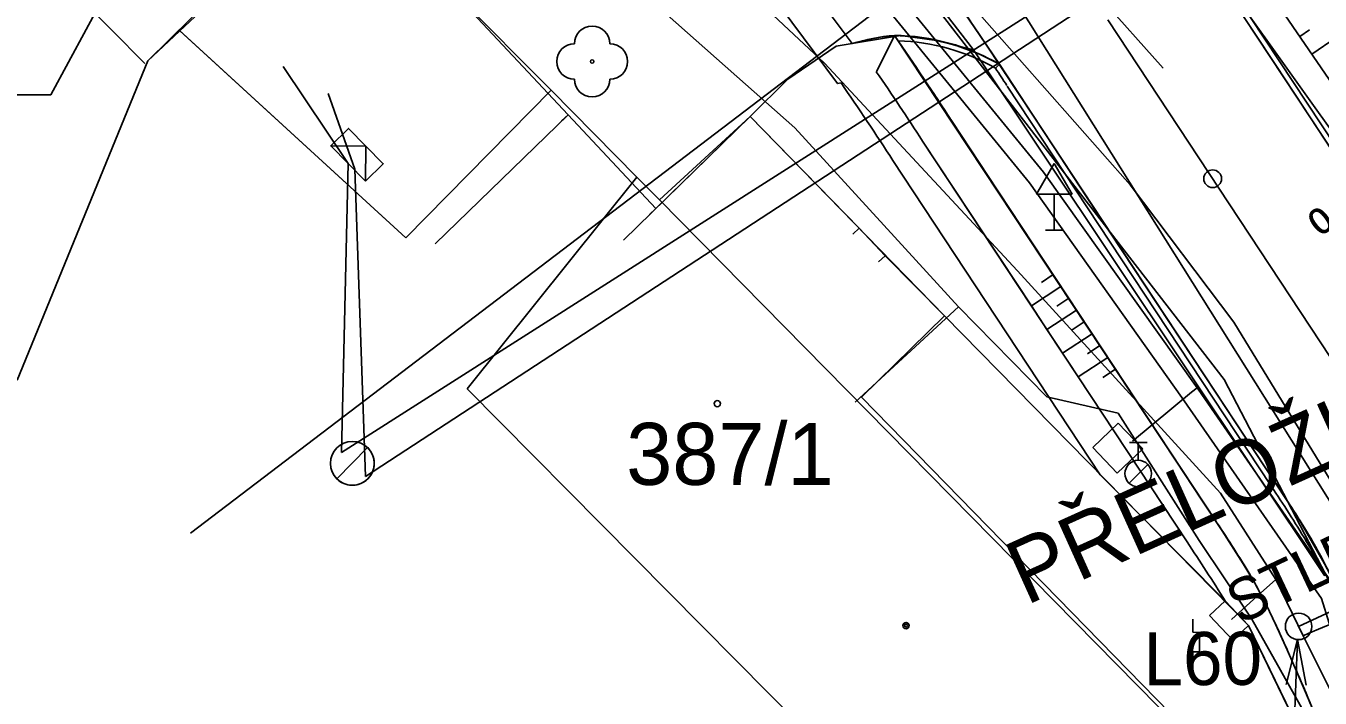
# Model space of a CAD drawing. Extents: x -643342 to -638635, y -1201752 to -1189948.
# Drawn here: x -639555.87 to -639519.33, y -1192610.36 to -1192591.39 of the extents above; entities that cross this region are included whole.
import ezdxf

# ---------------------------------------------------------------- set-up
doc = ezdxf.new("R2010")
doc.units = 0
for name, color, linetype in [('2', 7, 'Continuous'), ('42', 7, 'Continuous'), ('IS_EL_NN_NADZEMNÍ', 7, 'Continuous'), ('IS_EL_NN_PODZEMNÍ', 7, 'Continuous'), ('IS_PLYN_STL', 7, 'Continuous'), ('IS_TELEF_MISTNI_ZAMERENO', 7, 'Continuous'), ('IS_VODOVOD_PRIPOJKA DOMOVNÍ', 7, 'Continuous'), ('IS_VODOVOD_VAS', 7, 'Continuous'), ('IS_VODOVOD_ZRUSENY', 7, 'Continuous'), ('K-HRANICE_KN', 7, 'Continuous'), ('K-ČÍSLA_PARCEL', 7, 'Continuous'), ('N-CHODNIK', 7, 'Continuous'), ('N-HECTOMETRY', 7, 'Continuous'), ('N-KAN_DEST_TRASA-NÁVRH', 7, 'Continuous'), ('N-OBVOD STAVBY 06', 7, 'Continuous'), ('N-OSA', 7, 'Continuous'), ('N-SILNICE', 7, 'Continuous'), ('N-SJEZDY', 7, 'Continuous'), ('N-SO101_KLOPENI', 7, 'Continuous'), ('N-SRAFY_PLOCHY', 7, 'Continuous'), ('N-SVAHOVÁNÍ', 7, 'Continuous'), ('RWE_STL_RADY', 7, 'Continuous'), ('Vrstva 46', 7, 'Continuous'), ('Z-budovy', 7, 'Continuous'), ('Z-hrany_a_čáry', 7, 'Continuous'), ('Z-stromy', 7, 'Continuous'), ('Z-vchody_vjezdy', 7, 'Continuous'), ('Z-značky', 7, 'Continuous'), ('Z-šachty_poklopy', 7, 'Continuous')]:
    doc.layers.add(name, color=color, linetype=linetype)

# ---------------------------------------------------------------- blocks, each defined once
blk = doc.blocks.new('hecto2')
at = {"layer": 'N-HECTOMETRY'}
blk.add_circle((0, 0), 0.25, dxfattribs=at)

msp = doc.modelspace()

# ---------------------------------------------------------------- linework, layer by layer
at = {"layer": '2'}
msp.add_circle((-639519.932, -1192608.331), 0.375, dxfattribs=at)
at = {"layer": '42'}
for p, q in [((-639555.166, -1192593.331), (-639544.715, -1192573.992)), ((-639540.313, -1192573.957), (-639523.758, -1192592.58)), ((-639577.063, -1192593.331), (-639555.166, -1192593.331)), ((-639519.963, -1192608.704), (-639520.287, -1192609.969)), ((-639520.256, -1192616.346), (-639519.963, -1192608.704)), ((-639519.963, -1192608.704), (-639519.716, -1192609.987))]:
    msp.add_line(p, q, dxfattribs=at)
at = {"layer": 'IS_EL_NN_NADZEMNÍ'}
for p, q in [((-639520.2, -1192587.08), (-639546.28, -1192604.1)), ((-639521.55, -1192587.25), (-639546.96, -1192603.42)), ((-639546.96, -1192603.42), (-639546.77, -1192595.27)), ((-639546.28, -1192604.1), (-639546.58, -1192595.43))]:
    msp.add_line(p, q, dxfattribs=at)
for points in [[(-639546.279, -1192595.768), (-639546.271, -1192594.779), (-639547.26, -1192594.771)], [(-639547.09, -1192604.167), (-639546.224, -1192603.279)], [(-639546.224, -1192603.279), (-639547.09, -1192604.167)]]:
    msp.add_lwpolyline(points, dxfattribs=at)
msp.add_circle((-639546.65, -1192603.73), 0.62, dxfattribs=at)
for centre, radius, start, end in [((-639546.65, -1192603.73), 0.62, 224.818, 45.737), ((-639546.677, -1192603.71), 0.625, 42.6813, 43.6055)]:
    msp.add_arc(centre, radius, start, end, dxfattribs=at)
at = {"layer": 'IS_EL_NN_PODZEMNÍ'}
for p, q in [((-639546.77, -1192595.27), (-639548.6, -1192592.53)), ((-639546.58, -1192595.43), (-639547.33, -1192593.29))]:
    msp.add_line(p, q, dxfattribs=at)
msp.add_lwpolyline([(-639546.279, -1192595.768), (-639547.26, -1192594.771), (-639546.762, -1192594.279), (-639545.779, -1192595.277)], close=True, dxfattribs=at)
at = {"layer": 'IS_PLYN_STL'}
for points in [[(-639559.68, -1192568.38), (-639559.46, -1192568.55), (-639554.43, -1192572.9), (-639553.3, -1192573.86), (-639548.93, -1192577.94), (-639546.47, -1192580.23), (-639545.93, -1192580.74), (-639537.37, -1192588.65), (-639533.32, -1192592.44), (-639527.87, -1192598.3), (-639522.14, -1192604.57), (-639520.58, -1192607.01), (-639519.8, -1192608.6)], [(-639519.8, -1192608.6), (-639519.66, -1192608.53), (-639519.26, -1192608.36), (-639509.44, -1192604.37), (-639509.29, -1192604.31), (-639498.2, -1192598.48), (-639497.397, -1192598.104)], [(-639521.83, -1192608.14), (-639521.09, -1192607.47), (-639520.58, -1192607.01)], [(-639519.8, -1192608.6), (-639518.34, -1192611.53), (-639516.3, -1192616.88), (-639515.62, -1192620.55), (-639513.67, -1192631.06), (-639513.06, -1192634.97), (-639512.85, -1192638.89), (-639512.56, -1192644.42), (-639512.26, -1192649.59)]]:
    msp.add_lwpolyline(points, dxfattribs=at)
at = {"layer": 'IS_TELEF_MISTNI_ZAMERENO'}
for p, q in [((-639538.52, -1192590.4), (-639534.16, -1192594.26)), ((-639534.16, -1192594.26), (-639538.52, -1192590.4)), ((-639534.16, -1192594.26), (-639529.54, -1192599.31)), ((-639529.54, -1192599.31), (-639532.45, -1192602)), ((-639529.54, -1192599.31), (-639527.04, -1192601.85)), ((-639527.04, -1192601.85), (-639525.03, -1192602.31)), ((-639525.03, -1192602.31), (-639522.74, -1192605.91)), ((-639522.74, -1192605.91), (-639521.25, -1192608.13)), ((-639521.25, -1192608.13), (-639519.63, -1192611.01))]:
    msp.add_line(p, q, dxfattribs=at)
at = {"layer": 'IS_VODOVOD_PRIPOJKA DOMOVNÍ'}
for points in [[(-639531.24, -1192590.494), (-639531.458, -1192590.659), (-639551.224, -1192605.705)], [(-639522.796, -1192601.597), (-639522.96, -1192601.719), (-639524.621, -1192603.109)]]:
    msp.add_lwpolyline(points, dxfattribs=at)
at = {"layer": 'IS_VODOVOD_VAS'}
for points in [[(-639574.178, -1192545), (-639565.32, -1192554.2), (-639544.196, -1192576.345), (-639543.991, -1192576.56), (-639543.73, -1192576.83), (-639534.504, -1192586.506), (-639531.24, -1192590.494), (-639527.133, -1192595.51), (-639522.796, -1192601.597), (-639522.77, -1192601.637), (-639518.91, -1192607.22), (-639515.881, -1192615.376)], [(-639574.504, -1192545.287), (-639565.62, -1192554.6), (-639534.876, -1192586.834), (-639527.527, -1192595.81), (-639523.229, -1192601.871), (-639519.29, -1192607.54), (-639519.07, -1192608.24), (-639516.818, -1192614.307), (-639515.63, -1192618.18), (-639513.05, -1192632.38), (-639511.6, -1192653.11)]]:
    msp.add_lwpolyline(points, dxfattribs=at)
at = {"layer": 'IS_VODOVOD_ZRUSENY'}
msp.add_lwpolyline([(-639573.944, -1192546.368), (-639550.08, -1192573.56), (-639545.32, -1192575.03), (-639544.04, -1192576.59), (-639530.53, -1192590.38), (-639522.03, -1192601.36), (-639515.23, -1192614.43)], dxfattribs=at)
at = {"layer": 'K-HRANICE_KN'}
for p, q in [((-639524.691, -1192595.875), (-639564.643, -1192550.549)), ((-639524.691, -1192595.875), (-639564.643, -1192550.549)), ((-639567.14, -1192577.61), (-639552.51, -1192592.45)), ((-639567.14, -1192577.61), (-639552.51, -1192592.45)), ((-639547.1, -1192587.1), (-639552.423, -1192592.372)), ((-639546.916, -1192587.206), (-639552.423, -1192592.372)), ((-639541.039, -1192593.2), (-639547.1, -1192587.1)), ((-639540.559, -1192593.892), (-639545.14, -1192589)), ((-639551.544, -1192591.501), (-639545.14, -1192597.37)), ((-639551.519, -1192591.524), (-639545.14, -1192597.37)), ((-639552.423, -1192592.372), (-639556.111, -1192601.382)), ((-639552.423, -1192592.372), (-639556.111, -1192601.382)), ((-639545.14, -1192597.37), (-639541.039, -1192593.2)), ((-639538.619, -1192595.65), (-639541.04, -1192593.2)), ((-639538.079, -1192596.54), (-639540.559, -1192593.892)), ((-639535.42, -1192593.94), (-639538.079, -1192596.54)), ((-639535.42, -1192593.94), (-639537.98, -1192596.29)), ((-639529.93, -1192599.57), (-639535.42, -1192593.94)), ((-639529.93, -1192599.57), (-639535.42, -1192593.94)), ((-639538.619, -1192595.65), (-639543.41, -1192601.63)), ((-639537.98, -1192596.29), (-639538.619, -1192595.65)), ((-639521.759, -1192599.745), (-639524.691, -1192595.875)), ((-639521.759, -1192599.745), (-639524.691, -1192595.875)), ((-639537.98, -1192596.29), (-639516.86, -1192617.73)), ((-639521.35, -1192608.31), (-639529.93, -1192599.57)), ((-639521.35, -1192608.31), (-639529.93, -1192599.57)), ((-639518.131, -1192605.698), (-639521.759, -1192599.745)), ((-639518.131, -1192605.698), (-639521.759, -1192599.745)), ((-639543.41, -1192601.63), (-639522.19, -1192623.03)), ((-639516.79, -1192617.7), (-639521.35, -1192608.31))]:
    msp.add_line(p, q, dxfattribs=at)
at = {"layer": 'K-ČÍSLA_PARCEL'}
msp.add_circle((-639536.346, -1192602.046), 0.0875, dxfattribs=at)
msp.add_circle((-639536.346, -1192602.046), 0.0875, dxfattribs=at)
at = {"layer": 'N-CHODNIK'}
for p, q in [((-639529.724, -1192594.071), (-639529.703, -1192594.103)), ((-639522.262, -1192605.373), (-639529.703, -1192594.103)), ((-639522.262, -1192605.373), (-639522.238, -1192605.409)), ((-639520.127, -1192609.285), (-639520.113, -1192609.317)), ((-639520.113, -1192609.317), (-639520.092, -1192609.366)), ((-639520.092, -1192609.366), (-639520.074, -1192609.405))]:
    msp.add_line(p, q, dxfattribs=at)
for centre, radius, start, end in [((-639612.668, -1192647.965), 98.915, 33.01474, 34.70003), ((-639551.076, -1192624.797), 34.75, 31.0476, 33.9124), ((-639534.027, -1192614.34), 14.75, 26.5913, 30.5725), ((-639554.655, -1192624.188), 37.606, 23.3469, 26.0207), ((-639551.769, -1192623.654), 34.75, 21.3416, 24.2064)]:
    msp.add_arc(centre, radius, start, end, dxfattribs=at)
at = {"layer": 'N-KAN_DEST_TRASA-NÁVRH'}
msp.add_lwpolyline([(-639583.962, -1192528.01), (-639550.452, -1192564.184), (-639529.583, -1192588.026), (-639514.491, -1192612.048), (-639507.737, -1192644.326), (-639498.832, -1192694.254), (-639511.439, -1192713.331), (-639516.613, -1192716.507), (-639553.938, -1192703.739), (-639570.485, -1192701.616), (-639578.687, -1192703.18)], dxfattribs=at)
at = {"layer": 'N-OBVOD STAVBY 06'}
for points in [[(-639532.853, -1192592.991), (-639532.948, -1192593.015), (-639536.515, -1192588.213), (-639537.119, -1192588.308), (-639546.267, -1192578.054), (-639553.229, -1192570.356), (-639556.749, -1192566.564), (-639568.569, -1192553.875), (-639568.389, -1192552.802), (-639591.813, -1192527.078)], [(-639515.5, -1192654.75), (-639516.47, -1192621.08), (-639517.265, -1192621.777), (-639518.094, -1192619.759), (-639518.344, -1192619.397), (-639517.68, -1192618.58), (-639516.79, -1192617.7), (-639516.79, -1192617.7), (-639518.486, -1192614.207), (-639519.776, -1192611.551), (-639521.35, -1192608.31), (-639522.01, -1192607.61), (-639525.532, -1192604.05), (-639525.532, -1192604.05), (-639531.387, -1192595.182)]]:
    msp.add_lwpolyline(points, dxfattribs=at)
msp.add_arc((-639612.668, -1192647.965), 96.915, 32.99931, 34.55757, dxfattribs=at)
at = {"layer": 'N-OSA'}
msp.add_lwpolyline([(-639517.881, -1192602.48), (-639525.322, -1192591.21)], dxfattribs=at)
at = {"layer": 'N-SILNICE'}
for p, q in [((-639515.169, -1192600.689), (-639522.61, -1192589.419)), ((-639515.176, -1192600.678), (-639522.603, -1192589.429)), ((-639515.044, -1192600.607), (-639522.485, -1192589.337)), ((-639528.382, -1192592.469), (-639528.488, -1192592.581)), ((-639520.718, -1192604.353), (-639528.159, -1192593.084)), ((-639520.593, -1192604.271), (-639528.034, -1192593.001))]:
    msp.add_line(p, q, dxfattribs=at)
for centre, radius, start, end in [((-639612.668, -1192647.965), 100.915, 33.01474, 35.76493), ((-639531.406, -1192597.674), 6.02, 59.8399, 89.4179), ((-639531.406, -1192597.674), 5.87, 60.1819, 88.377), ((-639612.668, -1192647.965), 100.765, 33.01474, 33.3417), ((-639612.668, -1192647.965), 100.915, 33.01474, 33.3619), ((-639551.076, -1192624.797), 36.6, 31.0476, 33.9124), ((-639551.076, -1192624.797), 36.75, 31.0476, 33.9124), ((-639534.027, -1192614.34), 16.75, 26.5913, 30.5725), ((-639534.027, -1192614.34), 16.6, 26.5913, 30.5725)]:
    msp.add_arc(centre, radius, start, end, dxfattribs=at)
at = {"layer": 'N-SJEZDY'}
msp.add_line((-639535.546, -1192587.841), (-639532.542, -1192591.885), dxfattribs=at)
msp.add_arc((-639530.837, -1192597.522), 5.89, 94.9496, 106.83, dxfattribs=at)
at = {"layer": 'N-SRAFY_PLOCHY'}
for p, q in [((-639535.546, -1192587.841), (-639532.542, -1192591.885)), ((-639522, -1192590.343), (-639521.058, -1192591.769)), ((-639529.612, -1192590.645), (-639528.798, -1192591.842)), ((-639520.578, -1192592.497), (-639521.83, -1192590.601)), ((-639528.382, -1192592.469), (-639529.391, -1192590.966)), ((-639532.542, -1192591.885), (-639532.081, -1192591.765)), ((-639532.081, -1192591.765), (-639531.735, -1192591.701)), ((-639531.345, -1192591.655), (-639531.855, -1192592.677)), ((-639531.735, -1192591.701), (-639531.345, -1192591.655)), ((-639530.898, -1192591.676), (-639531.345, -1192591.655)), ((-639531.345, -1192591.655), (-639523.386, -1192603.671)), ((-639531.345, -1192591.655), (-639530.714, -1192591.694)), ((-639530.456, -1192591.73), (-639530.898, -1192591.676)), ((-639530.714, -1192591.694), (-639530.118, -1192591.794)), ((-639529.652, -1192591.916), (-639530.456, -1192591.73)), ((-639530.118, -1192591.794), (-639529.571, -1192591.946)), ((-639528.942, -1192592.182), (-639529.652, -1192591.916)), ((-639529.571, -1192591.946), (-639529.21, -1192592.069)), ((-639528.798, -1192591.842), (-639527.803, -1192593.35)), ((-639521.058, -1192591.769), (-639520.032, -1192593.323)), ((-639529.21, -1192592.069), (-639528.828, -1192592.234)), ((-639528.382, -1192592.469), (-639528.942, -1192592.182)), ((-639528.828, -1192592.234), (-639528.581, -1192592.358)), ((-639528.581, -1192592.358), (-639528.382, -1192592.469)), ((-639525.918, -1192596.207), (-639528.382, -1192592.469)), ((-639518.893, -1192595.049), (-639520.578, -1192592.497)), ((-639527.803, -1192593.35), (-639526.707, -1192595.011)), ((-639520.032, -1192593.323), (-639518.984, -1192594.911)), ((-639526.644, -1192598.736), (-639529.714, -1192594.087)), ((-639530.55, -1192594.634), (-639527.478, -1192599.287)), ((-639526.707, -1192595.011), (-639525.25, -1192597.217)), ((-639520.244, -1192604.799), (-639525.918, -1192596.207)), ((-639525.25, -1192597.217), (-639523.653, -1192599.636)), ((-639526.644, -1192598.736), (-639527.478, -1192599.287)), ((-639527.478, -1192599.287), (-639526.644, -1192598.736)), ((-639527.478, -1192599.287), (-639527.038, -1192599.955)), ((-639523.653, -1192599.636), (-639522.186, -1192601.859)), ((-639525.321, -1192600.739), (-639526.156, -1192601.29)), ((-639526.156, -1192601.29), (-639525.321, -1192600.739)), ((-639526.156, -1192601.29), (-639523.082, -1192605.946)), ((-639522.186, -1192601.859), (-639521.167, -1192603.402)), ((-639523.386, -1192603.671), (-639522.663, -1192604.765)), ((-639521.167, -1192603.402), (-639519.986, -1192605.202)), ((-639522.663, -1192604.765), (-639522.088, -1192605.634)), ((-639519.591, -1192605.843), (-639520.244, -1192604.799)), ((-639519.986, -1192605.202), (-639519.063, -1192606.813)), ((-639522.088, -1192605.634), (-639521.495, -1192606.563)), ((-639518.968, -1192607.01), (-639519.591, -1192605.843)), ((-639521.495, -1192606.563), (-639521.177, -1192607.097)), ((-639521.177, -1192607.097), (-639520.837, -1192607.737)), ((-639520.837, -1192607.737), (-639520.503, -1192608.443)), ((-639520.503, -1192608.443), (-639520.216, -1192609.081)), ((-639520.216, -1192609.081), (-639519.875, -1192609.856)), ((-639519.875, -1192609.856), (-639519.57, -1192610.585))]:
    msp.add_line(p, q, dxfattribs=at)
for points in [[(-639527.038, -1192599.955), (-639526.203, -1192599.404), (-639526.644, -1192598.736)], [(-639526.597, -1192600.623), (-639525.762, -1192600.072), (-639526.203, -1192599.404), (-639527.038, -1192599.955), (-639526.597, -1192600.623)], [(-639525.321, -1192600.739), (-639525.762, -1192600.072), (-639526.597, -1192600.623), (-639526.156, -1192601.29)], [(-639522.238, -1192605.409), (-639522.262, -1192605.373), (-639525.321, -1192600.739)], [(-639522.01, -1192607.61), (-639521.35, -1192608.31), (-639518.486, -1192614.207), (-639518.647, -1192613.573), (-639518.657, -1192613.53)], [(-639520.074, -1192609.405), (-639520.092, -1192609.366), (-639520.113, -1192609.317), (-639520.127, -1192609.285)]]:
    msp.add_lwpolyline(points, dxfattribs=at)
for centre, radius, start, end in [((-639612.668, -1192647.965), 98.915, 33.00373, 34.70003), ((-639612.668, -1192647.965), 97.915, 33.00154, 34.37816), ((-639551.076, -1192624.797), 34.75, 31.085, 33.9124), ((-639573.002, -1192639.283), 60.028, 31.84594, 33.7348), ((-639534.027, -1192614.34), 14.75, 26.6885, 30.4914), ((-639554.655, -1192624.188), 37.606, 23.3469, 25.9792), ((-639551.769, -1192623.654), 34.75, 21.379, 24.2064)]:
    msp.add_arc(centre, radius, start, end, dxfattribs=at)
at = {"layer": 'N-SVAHOVÁNÍ'}
for p, q in [((-639531.345, -1192591.655), (-639531.855, -1192592.677)), ((-639527.196, -1192598.622), (-639526.864, -1192598.403)), ((-639527.478, -1192599.287), (-639526.644, -1192598.736)), ((-639526.763, -1192599.294), (-639526.423, -1192599.07)), ((-639527.038, -1192599.955), (-639526.203, -1192599.404)), ((-639526.329, -1192599.967), (-639525.983, -1192599.738)), ((-639526.597, -1192600.623), (-639525.762, -1192600.072)), ((-639526.156, -1192601.29), (-639525.321, -1192600.739)), ((-639525.896, -1192600.639), (-639525.542, -1192600.405)), ((-639525.463, -1192601.312), (-639525.101, -1192601.073))]:
    msp.add_line(p, q, dxfattribs=at)
for points in [[(-639530.55, -1192594.634), (-639523.082, -1192605.946)], [(-639522.01, -1192607.61), (-639521.35, -1192608.31), (-639518.486, -1192614.207)]]:
    msp.add_lwpolyline(points, dxfattribs=at)
for centre, radius, start, end in [((-639612.668, -1192647.965), 97.915, 33.00154, 34.37816), ((-639573.002, -1192639.283), 60.028, 31.84594, 33.7348)]:
    msp.add_arc(centre, radius, start, end, dxfattribs=at)
at = {"layer": 'RWE_STL_RADY'}
msp.add_lwpolyline([(-639519.932, -1192608.331), (-639509.165, -1192603.343), (-639508.236, -1192603.756)], dxfattribs=at)
at = {"layer": 'Z-budovy'}
for p, q in [((-639540.559, -1192593.892), (-639544.525, -1192589.657)), ((-639544.313, -1192597.54), (-639540.559, -1192593.892)), ((-639538.995, -1192597.436), (-639535.42, -1192593.94)), ((-639535.42, -1192593.94), (-639532.34, -1192597.09)), ((-639532.34, -1192597.09), (-639531.61, -1192597.87)), ((-639531.61, -1192597.87), (-639529.93, -1192599.57)), ((-639529.93, -1192599.57), (-639532.275, -1192601.863)), ((-639532.275, -1192601.863), (-639516.79, -1192617.7))]:
    msp.add_line(p, q, dxfattribs=at)
at = {"layer": 'Z-hrany_a_čáry'}
for p, q in [((-639513.31, -1192602.34), (-639526.36, -1192584.02)), ((-639512.51, -1192602.5), (-639522.24, -1192588.26)), ((-639529.11, -1192592.06), (-639531.73, -1192588.66)), ((-639519.9, -1192591.683), (-639519.624, -1192591.495)), ((-639534.351, -1192592.885), (-639532.99, -1192591.96)), ((-639532.99, -1192591.96), (-639531.171, -1192591.655)), ((-639531.171, -1192591.655), (-639530.16, -1192591.8)), ((-639530.16, -1192591.8), (-639529.11, -1192592.06)), ((-639519.562, -1192592.179), (-639518.874, -1192591.709)), ((-639529.11, -1192592.06), (-639519.2, -1192606.9)), ((-639535.42, -1192593.94), (-639534.351, -1192592.885)), ((-639522.01, -1192607.61), (-639522.447, -1192608.022)), ((-639521.35, -1192608.31), (-639522.01, -1192607.61)), ((-639522.447, -1192608.022), (-639521.787, -1192608.722)), ((-639521.787, -1192608.722), (-639521.35, -1192608.31)), ((-639521.35, -1192608.31), (-639516.79, -1192617.7))]:
    msp.add_line(p, q, dxfattribs=at)
at = {"layer": 'Z-stromy'}
msp.add_circle((-639539.88, -1192592.39), 0.05, dxfattribs=at)
for centre, start, end in [((-639539.88, -1192591.89), 0, 180), ((-639540.38, -1192592.39), 90, 270), ((-639539.38, -1192592.39), 270, 90), ((-639539.88, -1192592.89), 180, 0)]:
    msp.add_arc(centre, 0.5, start, end, dxfattribs=at)
at = {"layer": 'Z-vchody_vjezdy'}
for p, q in [((-639540.741, -1192594.063), (-639540.559, -1192593.892)), ((-639538.079, -1192596.54), (-639540.559, -1192593.892)), ((-639538.261, -1192596.711), (-639538.079, -1192596.54)), ((-639532.523, -1192597.261), (-639532.34, -1192597.09)), ((-639531.61, -1192597.87), (-639532.34, -1192597.09)), ((-639531.793, -1192598.041), (-639531.61, -1192597.87))]:
    msp.add_line(p, q, dxfattribs=at)
at = {"layer": 'Z-značky'}
for p, q in [((-639526.83, -1192595.266), (-639527.33, -1192596.132)), ((-639526.33, -1192596.132), (-639526.83, -1192595.266)), ((-639527.33, -1192596.132), (-639526.33, -1192596.132)), ((-639526.83, -1192596.132), (-639526.83, -1192597.15)), ((-639527.08, -1192597.15), (-639526.58, -1192597.15)), ((-639524.71, -1192603.145), (-639524.21, -1192603.145)), ((-639524.46, -1192603.645), (-639524.46, -1192603.145)), ((-639524.718, -1192604.292), (-639524.188, -1192603.762)), ((-639522.915, -1192608.499), (-639522.916, -1192608.131)), ((-639522.732, -1192608.5), (-639522.915, -1192608.499)), ((-639522.732, -1192609.052), (-639522.732, -1192608.5)), ((-639522.916, -1192609.42), (-639522.915, -1192609.052)), ((-639522.915, -1192609.052), (-639522.732, -1192609.052))]:
    msp.add_line(p, q, dxfattribs=at)
for centre, radius in [((-639524.46, -1192604.02), 0.375), ((-639531.017, -1192608.31), 0.09), ((-639531.017, -1192608.31), 0.0398)]:
    msp.add_circle(centre, radius, dxfattribs=at)
at = {"layer": 'Z-šachty_poklopy'}
for p, q in [((-639525.023, -1192602.593), (-639525.747, -1192603.283)), ((-639524.333, -1192603.317), (-639525.023, -1192602.593)), ((-639525.747, -1192603.283), (-639525.057, -1192604.007)), ((-639525.057, -1192604.007), (-639524.333, -1192603.317))]:
    msp.add_line(p, q, dxfattribs=at)

# ---------------------------------------------------------------- block references
at = {"layer": 'N-HECTOMETRY', "rotation": 123.43492524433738}
msp.add_blockref('hecto2', (-639522.359, -1192595.697), dxfattribs=at)

# ---------------------------------------------------------------- texts
at = {"layer": '2'}
msp.add_text('PŘELOŽKA 6 STL', height=1.8, rotation=24.2931, dxfattribs=at).set_placement((-639527.629, -1192607.75))
at = {"layer": 'K-ČÍSLA_PARCEL'}
msp.add_text('387/1', height=1.75, dxfattribs=at).set_placement((-639538.918, -1192604.338))
msp.add_text('387/1', height=1.75, dxfattribs=at).set_placement((-639538.918, -1192604.338))
at = {"layer": 'N-SO101_KLOPENI'}
msp.add_text('1.50%', height=1.2, rotation=217.0323, dxfattribs=at).set_placement((-639516.152, -1192594.035))
at = {"layer": 'RWE_STL_RADY'}
msp.add_text('STLPE 63 - 12,88 m', height=1.2, rotation=25.2816, dxfattribs=at).set_placement((-639521.593, -1192608.292))
at = {"layer": 'Vrstva 46'}
msp.add_text('L60', height=1.5, rotation=0.301, dxfattribs=at).set_placement((-639524.307, -1192609.997))

doc.saveas('drawing.dxf')
